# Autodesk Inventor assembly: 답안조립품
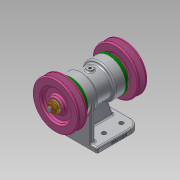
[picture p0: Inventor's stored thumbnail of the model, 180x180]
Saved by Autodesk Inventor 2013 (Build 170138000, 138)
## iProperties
Created: 2020-06
Part Number: 답안조립품
Document SubType Name: Assembly
Designer: a
Author: a
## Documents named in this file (12)
- C:\Users\a\Desktop\700606V1005\답안조립품.iam
- C:\Users\a\Desktop\700606V1005\본체.ipt
- C:\Users\a\Desktop\700606V1005\Ű 5x5x12.ipt
- C:\Users\a\Desktop\700606V1005\V-벨트풀리.ipt
- C:\Users\a\Desktop\700606V1005\너트 M10.ipt
- C:\Users\a\Desktop\700606V1005\베어링 6204.ipt
- C:\Users\a\Desktop\700606V1005\볼트 M4.ipt
- C:\Users\a\Desktop\700606V1005\스프링 와셔 10.ipt
- C:\Users\a\Desktop\700606V1005\오일 실 20 32 5.ipt
- C:\Users\a\Desktop\700606V1005\축.ipt
- C:\Users\a\Desktop\700606V1005\커버.ipt
- C:\Users\a\Desktop\700606V1005\평면 와셔 10x21.ipt
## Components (4 placed, 2 different names)
1. Ű 5x5x12:1
2. V-벨트풀리:1
3. Ű 5x5x12:2
4. V-벨트풀리:2
